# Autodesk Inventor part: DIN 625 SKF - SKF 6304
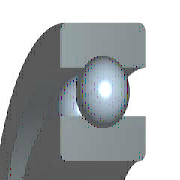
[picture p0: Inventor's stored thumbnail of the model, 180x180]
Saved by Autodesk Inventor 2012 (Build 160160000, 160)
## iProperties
Created: 2011-02
Part Number: DIN 625 SKF - SKF 6304
Material: Steel, Mild
Description: Single row ball bearings
Document SubType Name: Modeling
Standard: DIN 625
Designer: Admin
Standards Organization: DIN
Language: en-US
Size Designation: SKF 6304
Categories: <MemberInstance><Categories><Category DisplayName="Shaft Parts" InternalName="7f7aeb1f-a693-4053-b835-cee3144e0d98" Mnemonic="SHFT"><Category DisplayName="Beari
Density: 7.86 g/cm^3
IsCustomPart: 0
Author: Admin
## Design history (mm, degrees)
node "Sketch1"
node "WorkPoint1"
node "WorkAxis1"
node "WorkPlane3"
node "WorkPlane4"
node "Sketch4"
node "WorkPoint2"
pattern_circular "PolarArray1" dims "d17" = 60.25 (= msp_pocet), angle "d19" = 360 deg
fillet "Fillet1" dims "d20" = 1.1 (= r)
body "Solid1"
revolve "Revolution1" stored, may be unused: angle "d6" = 360 deg
revolve "Revolution2" stored, may be unused: angle "d10" = 360 deg
revolve "Revolution3" stored, may be unused: angle "d16" = 360 deg
sketch "Sketch2"
  geometry: L1 (10, 15)-(26, 15); L2 (10, 0)-(10, 15); L3 (26, 0)-(10, 0); L4 (26, 15)-(26, 0); L5 (0, 0)-(0, 20); L6 (0, 0)-(0, 20); L7 (-7.2, 0)-(43.2, 0) reference
  constraints: 12 end point, 3 vertical, 2 horizontal, 1 collinear, 1 other
  dimensions: "d1" = 20 diameter of L1.start L5 (= Diam); "d3" = 52 diameter of L1.end L5 (= DD); "d5" = 15 distance of L2.start L1.start (= msp_mdtd2)
sketch "Sketch3"
  geometry: L1 (20.88, 15)-(20.88, 11.34); L2 (15.12, 15)-(20.88, 15); L3 (15.12, 11.34)-(15.12, 15); L4 (15.12, 0)-(15.12, 3.66); L5 (20.88, 0)-(15.12, 0); L6 (20.88, 3.66)-(20.88, 0); L7 (26, 0)-(-26, 0) reference; L8 (26, 15)-(-26, 15) reference; L9 (0, -42.29)-(0, 61.29); L10 (0, 82.007)-(0, -63.007) reference; A1 r 4.8 centre (18, 7.5) between (20.88, 3.66) and (20.88, 11.34); A2 r 4.8 centre (18, 7.5) between (15.12, 11.34) and (15.12, 3.66)
  constraints: 14 end point, 4 collinear, 4 point on circle, 4 vertical, 2 centre point, 2 concentric, 2 horizontal, 2 point on line
  dimensions: "d9" = 9.6 diameter of A1 (= msp_mdtd6); "d21" = 15.12 distance between parallel lines of L9 L4 (= 0.5 x msp_d1); "d22" = 18 distance from line of L9 A1.centre (= 0.5 x msp_ds); "d23" = 20.88 distance between parallel lines of L9 L6 (= 0.5 x msp_dd1)
sketch "Sketch5"
  geometry: L1 (18, 2.7)-(18, 12.3); L2 (20.88, 0)-(-20.88, 0) reference; L3 (18, 2.7)-(18, 12.3); A1 r 4.8 centre (18, 7.5) between (18, 2.7) and (18, 12.3); A2 r 4.8 centre (18, 7.5) between (20.88, 3.66) and (20.88, 11.34) reference
  constraints: 4 end point, 2 point on circle, 1 centre point, 1 concentric, 1 vertical
  dimensions: "d13" = 0 horizontal distance of A1.centre L1.start; "d15" = 9.6001 diameter of A1 (computed from msp_mdtd6)
other parameters: "Diam" = 20 [user parameter; used in 3 equation terms], "DD" = 52 [user parameter; used in 3 equation terms], "B" = 15 [user parameter; used in 1 equation term], "r" = 1.1 [user parameter; used in 1 equation term], "msp_ds" = 36 (= 0.5 x Diam + 0.5 x DD) [user parameter; used in 5 equation terms], "msp_d0" = 9.6 (= -0.3 x Diam + 0.3 x DD) [user parameter; used in 4 equation terms], "msp_d1" = 30.24 (= msp_ds - 0.6 x msp_d0) [user parameter; used in 1 equation term], "msp_dd1" = 41.76 (= msp_ds + 0.6 x msp_d0) [user parameter; used in 1 equation term], "msp_pom" = 54 (= 1.5 x msp_ds) [user parameter; used in 1 equation term], "msp_mdtd2" = 15 (= B) [user parameter; used in 3 equation terms], "msp_mdtd4" = 36 (= msp_ds) [user parameter], "msp_mdtd6" = 9.6 (= msp_d0) [user parameter; used in 2 equation terms], "msp_mdtd7" = 7.5 (= 0.5 x msp_mdtd2) [user parameter], "msp_pocet" = 60.25 (computed from msp_d0, msp_pom) [user parameter; used in 1 equation term], "d2" = 72 (derived), "d4" = 19 (derived), "d7" = 0, "d8" = 15.6 (derived), "d11" = -15 (computed from msp_mdtd2), "d12" = 0 (derived), "d14" = 15.6001 (derived), "d26" = 0, "d27" = 0, "d28" = 0, "d29" = 0, "d30" = 0
